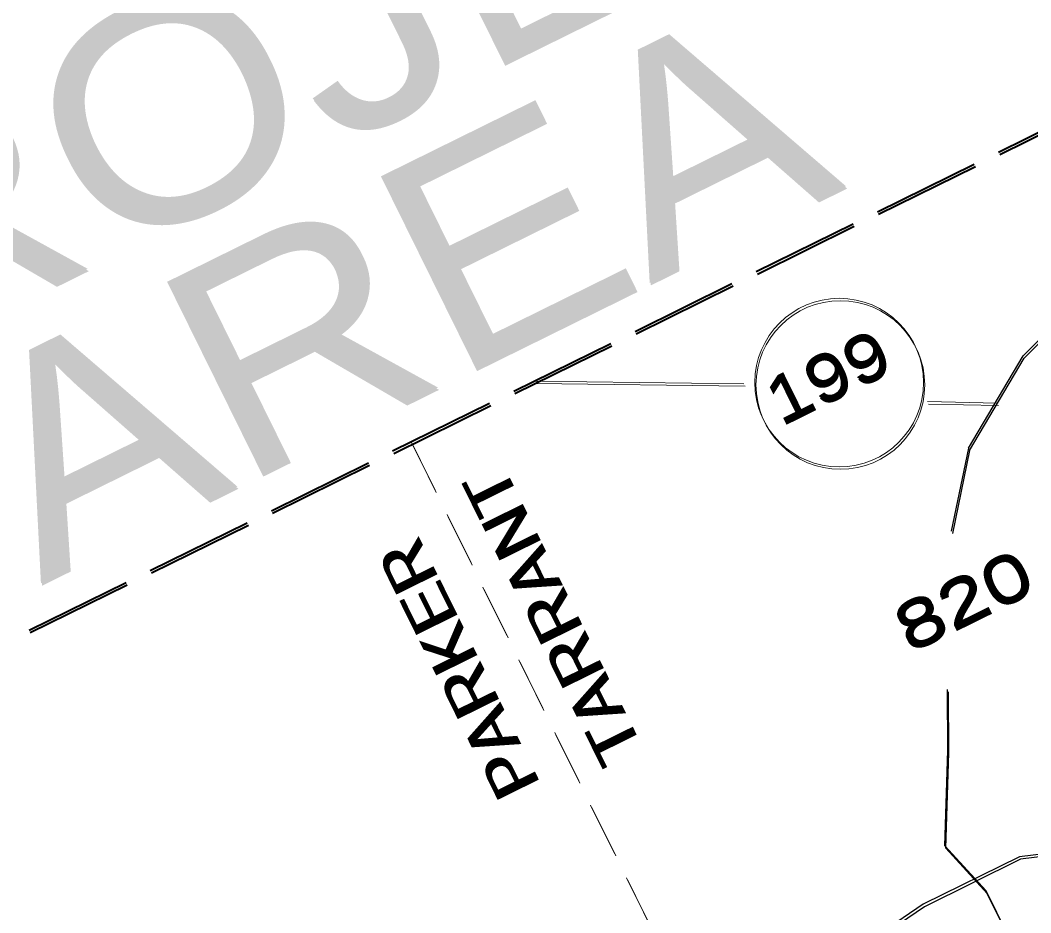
# Model space of a CAD drawing. Extents: x 2356606 to 2371222, y 6973096 to 6982644.
# Drawn here: x 2357117.5 to 2357229.6, y 6973619.6 to 6973718.7 of the extents above; entities that cross this region are included whole.
import ezdxf

# ---------------------------------------------------------------- set-up
doc = ezdxf.new("R2010")
doc.units = 0
doc.header["$LTSCALE"] = 2
doc.linetypes.add('LONG_DASHED', pattern=[7.5, 6, -1.5])
doc.linetypes.add('MEDIUM_DASHED', pattern=[4.5, 3, -1.5])
doc.layers.add('62', color=7, linetype='Continuous', lineweight=13)
doc.layers.add('63', color=7, linetype='Continuous', lineweight=13)

msp = doc.modelspace()

# ---------------------------------------------------------------- linework, layer by layer
at = {"layer": '62'}
for p, q in [((2357174.671, 6973678.357), (2357197.917, 6973678.037)), ((2357218.285, 6973676.07), (2357226.044, 6973675.908))]:
    msp.add_line(p, q, dxfattribs=at)
at = {"layer": '62', "linetype": 'MEDIUM_DASHED'}
msp.add_line((2357160.992, 6973671.606), (2357243.202, 6973505.087), dxfattribs=at)
at = {"layer": '62', "lineweight": 25}
for p, q in [((2357222.847, 6973670.893), (2357220.937, 6973661.694)), ((2357220.552, 6973637.313), (2357220.513, 6973644.097))]:
    msp.add_line(p, q, dxfattribs=at)
at = {"layer": '62', "linetype": 'LONG_DASHED', "lineweight": 40}
msp.add_lwpolyline([(2357063.437, 6973694.625), (2357091.678, 6973637.398), (2357247.577, 6973714.339), (2357219.335, 6973771.564), (2357063.154, 6973694.485)], dxfattribs=at)
at = {"layer": '62', "lineweight": 25}
for points in [[(2357222.847, 6973670.893), (2357228.918, 6973681.166), (2357239.427, 6973691.649), (2357246.285, 6973700.327), (2357253.234, 6973708.874), (2357262, 6973718.52), (2357266.949, 6973724.101), (2357275.91, 6973728.522), (2357290.215, 6973735.582), (2357301.579, 6973740.013), (2357308.151, 6973740.118), (2357312.029, 6973738.72)], [(2357397.532, 6973674.071), (2357391.187, 6973669.235), (2357382.618, 6973664.025), (2357370.494, 6973656.862), (2357361.535, 6973652.442), (2357355.506, 6973648.488), (2357352.272, 6973643.756), (2357344.159, 6973637.568), (2357331.099, 6973632.303), (2357319.179, 6973627.424), (2357306.189, 6973621.966), (2357287.579, 6973609.643), (2357267.547, 6973602.895), (2357250.669, 6973598.906), (2357239.274, 6973599.379), (2357230.661, 6973609.861), (2357224.807, 6973621.723), (2357220.224, 6973626.738), (2357220.552, 6973637.313)], [(2357242.801, 6973629.852), (2357237.017, 6973626.569), (2357228.509, 6973625.507), (2357217.835, 6973620.24), (2357195.98, 6973605.338)]]:
    msp.add_lwpolyline(points, dxfattribs=at)
at = {"layer": '62'}
msp.add_circle((2357208.499, 6973678.183), 9.364, dxfattribs=at)
at = {"layer": '63'}
for p, q in [((2357174.541, 6973678.62), (2357197.787, 6973678.3)), ((2357218.155, 6973676.333), (2357225.914, 6973676.171))]:
    msp.add_line(p, q, dxfattribs=at)
at = {"layer": '63', "linetype": 'MEDIUM_DASHED'}
msp.add_line((2357160.862, 6973671.869), (2357243.072, 6973505.35), dxfattribs=at)
at = {"layer": '63', "lineweight": 25}
for p, q in [((2357222.717, 6973671.156), (2357220.807, 6973661.957)), ((2357220.422, 6973637.576), (2357220.383, 6973644.36))]:
    msp.add_line(p, q, dxfattribs=at)
at = {"layer": '63', "linetype": 'LONG_DASHED', "lineweight": 40}
msp.add_lwpolyline([(2357063.307, 6973694.888), (2357091.548, 6973637.661), (2357247.447, 6973714.602), (2357219.205, 6973771.827), (2357063.024, 6973694.748)], dxfattribs=at)
at = {"layer": '63', "lineweight": 25}
for points in [[(2357222.717, 6973671.156), (2357228.788, 6973681.429), (2357239.297, 6973691.912), (2357246.155, 6973700.59), (2357253.104, 6973709.137), (2357261.87, 6973718.783), (2357266.819, 6973724.364), (2357275.78, 6973728.785), (2357290.085, 6973735.845), (2357301.449, 6973740.276), (2357308.021, 6973740.381), (2357311.899, 6973738.983)], [(2357397.402, 6973674.334), (2357391.057, 6973669.498), (2357382.488, 6973664.288), (2357370.364, 6973657.125), (2357361.405, 6973652.705), (2357355.376, 6973648.751), (2357352.142, 6973644.019), (2357344.029, 6973637.831), (2357330.969, 6973632.566), (2357319.049, 6973627.687), (2357306.059, 6973622.229), (2357287.449, 6973609.906), (2357267.417, 6973603.158), (2357250.539, 6973599.169), (2357239.144, 6973599.642), (2357230.531, 6973610.124), (2357224.677, 6973621.986), (2357220.094, 6973627.001), (2357220.422, 6973637.576)], [(2357242.671, 6973630.115), (2357236.887, 6973626.832), (2357228.379, 6973625.77), (2357217.705, 6973620.503), (2357195.85, 6973605.601)]]:
    msp.add_lwpolyline(points, dxfattribs=at)
at = {"layer": '63'}
msp.add_circle((2357208.369, 6973678.446), 9.364, dxfattribs=at)

# ---------------------------------------------------------------- texts
at = {"layer": '62'}
for s, height, rotation, width, p in [('PROJECT', 23.83, 26.268, 1.15, (2357080.956, 6973669.044)), ('AREA', 23.83, 26.268, 1.15, (2357119.831, 6973655.86)), ('199', 5.099, 26.268, 1.25, (2357201.947, 6973673.479)), ('TARRANT', 5.099, 116.268, 1.1, (2357186.757, 6973637.601)), ('PARKER', 5.099, 116.268, 1.1, (2357175.306, 6973633.806)), ('820', 5.099, 26.268, 1.4, (2357216.238, 6973648.286))]:
    msp.add_text(s, height=height, rotation=rotation, dxfattribs=dict(at, width=width)).set_placement(p)
at = {"layer": '63'}
for s, height, rotation, width, p in [('PROJECT', 23.83, 26.268, 1.15, (2357080.826, 6973669.308)), ('AREA', 23.83, 26.268, 1.15, (2357119.701, 6973656.124)), ('199', 5.099, 26.268, 1.25, (2357201.817, 6973673.743)), ('TARRANT', 5.099, 116.268, 1.1, (2357186.627, 6973637.865)), ('PARKER', 5.099, 116.268, 1.1, (2357175.176, 6973634.07)), ('820', 5.099, 26.268, 1.4, (2357216.108, 6973648.55))]:
    msp.add_text(s, height=height, rotation=rotation, dxfattribs=dict(at, width=width)).set_placement(p)

doc.saveas('drawing.dxf')
